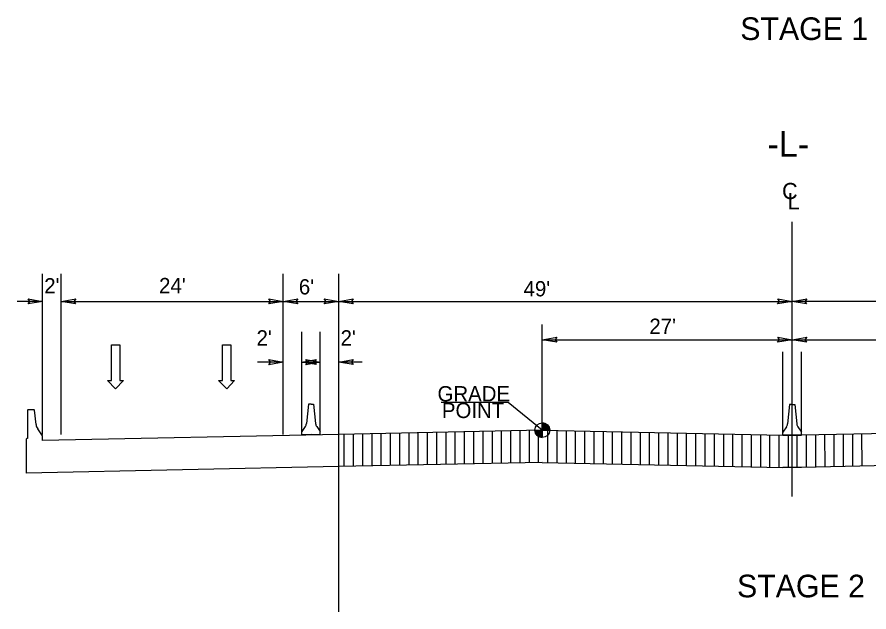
# Model space of a CAD drawing. Extents: x 2241081 to 2251104, y 658534 to 663427.
# Drawn here: x 2245916 to 2246330.3, y 660065.4 to 660354.9 of the extents above; entities that cross this region are included whole.
import ezdxf

# ---------------------------------------------------------------- set-up
doc = ezdxf.new("R2010")
doc.units = 0
for name, color, linetype in [('Prop Dimension', 7, 'Continuous'), ('Prop Dimension Text', 7, 'Continuous'), ('Prop Lane Arrow CELL', 7, 'Continuous'), ('Prop Roadway Bridge', 7, 'Continuous'), ('Typical Grade Point Symbol CELL', 7, 'Continuous'), ('Typical Median Barrier CELL', 7, 'Continuous'), ('Typical Terminator CELL', 7, 'Continuous'), ('Typical Text Centerline CELL', 7, 'Continuous'), ('Typical Text Grade Point CELL', 7, 'Continuous'), ('Typical Text Label CELL', 7, 'Continuous')]:
    doc.layers.add(name, color=color, linetype=linetype)

msp = doc.modelspace()

# ---------------------------------------------------------------- linework, layer by layer
at = {"layer": 'Prop Dimension'}
for p, q in [((2245928.42, 660151.8), (2245928.42, 660229.9)), ((2245937.42, 660151.8), (2245937.42, 660229.9)), ((2246045.42, 660164.32), (2246045.42, 660229.9)), ((2246072.42, 660151.8), (2246072.42, 660229.9)), ((2246054.42, 660164.32), (2246054.42, 660201.64)), ((2246063.42, 660164.32), (2246063.42, 660201.64)), ((2246288.42, 660152.98), (2246288.42, 660191.92)), ((2246297.42, 660152.98), (2246297.42, 660191.92))]:
    msp.add_line(p, q, dxfattribs=at)
at = {"layer": 'Prop Dimension Text'}
for p, q in [((2246045.42, 660151.8), (2246045.42, 660228.78)), ((2246072.42, 660152.36), (2246072.42, 660228.78)), ((2246072.42, 660065.43), (2246072.42, 660228.22)), ((2245928.42, 660216.54), (2245915.96, 660216.54)), ((2245937.42, 660216.54), (2246045.42, 660216.54)), ((2245937.42, 660216.54), (2245946.42, 660216.54)), ((2246045.42, 660216.54), (2246072.42, 660216.54)), ((2246072.42, 660216.54), (2246292.92, 660216.54)), ((2246531.42, 660216.54), (2246292.92, 660216.54)), ((2246171.42, 660153.86), (2246171.42, 660205.36)), ((2246171.42, 660197.89), (2246292.92, 660197.89)), ((2246292.92, 660197.89), (2246414.42, 660197.89)), ((2246054.42, 660152.36), (2246054.42, 660194.7)), ((2246063.42, 660152.36), (2246063.42, 660194.7)), ((2246045.42, 660186.98), (2246032.96, 660186.98)), ((2246054.42, 660186.98), (2246063.42, 660186.98)), ((2246083.84, 660186.98), (2246072.42, 660186.98)), ((2246075.11, 660136.2), (2246075.11, 660151.86)), ((2246079.61, 660136.29), (2246079.61, 660151.95)), ((2246084.11, 660136.38), (2246084.11, 660152.05)), ((2246088.61, 660136.48), (2246088.61, 660152.14)), ((2246093.11, 660136.57), (2246093.11, 660152.23)), ((2246097.61, 660136.66), (2246097.61, 660152.33)), ((2246102.11, 660136.76), (2246102.11, 660152.42)), ((2246106.61, 660136.85), (2246106.61, 660152.51)), ((2246111.11, 660136.94), (2246111.11, 660152.61)), ((2246115.61, 660137.04), (2246115.61, 660152.7)), ((2246120.11, 660137.13), (2246120.11, 660152.79)), ((2246124.61, 660137.22), (2246124.61, 660152.89)), ((2246129.11, 660137.32), (2246129.11, 660152.98)), ((2246133.61, 660137.41), (2246133.61, 660153.08)), ((2246138.11, 660137.51), (2246138.11, 660153.17)), ((2246142.61, 660137.6), (2246142.61, 660153.26)), ((2246147.11, 660137.69), (2246147.11, 660153.36)), ((2246151.61, 660137.79), (2246151.61, 660153.45)), ((2246156.11, 660137.88), (2246156.11, 660153.54)), ((2246160.61, 660137.97), (2246160.61, 660153.64)), ((2246165.11, 660138.07), (2246165.11, 660153.73)), ((2246169.61, 660138.16), (2246169.61, 660153.82)), ((2246174.11, 660138.14), (2246174.11, 660153.81)), ((2246178.61, 660138.05), (2246178.61, 660153.71)), ((2246183.11, 660137.95), (2246183.11, 660153.62)), ((2246187.61, 660137.86), (2246187.61, 660153.53)), ((2246192.11, 660137.77), (2246192.11, 660153.43)), ((2246196.61, 660137.67), (2246196.61, 660153.34)), ((2246201.11, 660137.58), (2246201.11, 660153.24)), ((2246205.61, 660137.49), (2246205.61, 660153.15)), ((2246210.11, 660137.39), (2246210.11, 660153.06)), ((2246214.61, 660137.3), (2246214.61, 660152.96)), ((2246219.11, 660137.21), (2246219.11, 660152.87)), ((2246223.61, 660137.11), (2246223.61, 660152.78)), ((2246228.11, 660137.02), (2246228.11, 660152.68)), ((2246232.61, 660136.93), (2246232.61, 660152.59)), ((2246237.11, 660136.83), (2246237.11, 660152.5)), ((2246241.61, 660136.74), (2246241.61, 660152.4)), ((2246246.11, 660136.64), (2246246.11, 660152.31)), ((2246250.61, 660136.55), (2246250.61, 660152.21)), ((2246255.11, 660136.46), (2246255.11, 660152.12)), ((2246259.61, 660136.36), (2246259.61, 660152.03)), ((2246264.11, 660136.27), (2246264.11, 660151.93)), ((2246268.61, 660136.18), (2246268.61, 660151.84)), ((2246317.89, 660136.19), (2246317.87, 660151.85)), ((2246322.39, 660136.28), (2246322.37, 660151.95)), ((2246326.89, 660136.38), (2246326.87, 660152.04)), ((2246273.11, 660136.08), (2246273.11, 660151.75)), ((2246277.61, 660135.99), (2246277.61, 660151.65)), ((2246282.11, 660135.9), (2246282.11, 660151.56)), ((2246286.61, 660135.8), (2246286.61, 660151.47)), ((2246291.11, 660135.76), (2246291.11, 660151.43)), ((2246295.39, 660135.76), (2246295.37, 660151.43)), ((2246299.89, 660135.82), (2246299.87, 660151.48)), ((2246304.39, 660135.91), (2246304.37, 660151.57)), ((2246308.89, 660136), (2246308.87, 660151.67)), ((2246313.39, 660136.1), (2246313.37, 660151.76))]:
    msp.add_line(p, q, dxfattribs=at)
at = {"layer": 'Prop Lane Arrow CELL'}
for p, q in [((2245961.82, 660177.97), (2245961.82, 660195.33)), ((2245961.82, 660195.33), (2245965.91, 660195.33)), ((2245965.91, 660195.33), (2245965.91, 660177.97)), ((2246015.82, 660177.97), (2246015.82, 660195.33)), ((2246015.82, 660195.33), (2246019.91, 660195.33)), ((2246019.91, 660195.33), (2246019.91, 660177.97)), ((2245963.92, 660174.06), (2245959.95, 660177.97)), ((2245959.95, 660177.97), (2245961.82, 660177.97)), ((2245967.77, 660177.97), (2245963.92, 660174.06)), ((2245965.91, 660177.97), (2245967.77, 660177.97)), ((2246017.92, 660174.06), (2246013.95, 660177.97)), ((2246013.95, 660177.97), (2246015.82, 660177.97)), ((2246021.77, 660177.97), (2246017.92, 660174.06)), ((2246019.91, 660177.97), (2246021.77, 660177.97))]:
    msp.add_line(p, q, dxfattribs=at)
at = {"layer": 'Prop Roadway Bridge'}
for p, q in [((2245921.18, 660163.75), (2245921.01, 660163.59)), ((2245921.01, 660163.59), (2245921.01, 660149.82)), ((2245924.33, 660163.75), (2245921.18, 660163.75)), ((2245924.52, 660163.57), (2245924.33, 660163.75)), ((2245925.25, 660156.6), (2245924.52, 660163.57)), ((2245928.42, 660151.12), (2245926.01, 660154.56)), ((2246171.42, 660153.86), (2246072.42, 660151.8)), ((2246171.42, 660153.86), (2246288.42, 660151.43)), ((2246414.42, 660153.86), (2246297.42, 660151.43)), ((2245920.69, 660149.82), (2245920.36, 660149.49)), ((2245920.36, 660149.49), (2245920.36, 660147.2)), ((2245921.01, 660149.82), (2245920.69, 660149.82)), ((2246072.42, 660151.8), (2245928.42, 660148.81)), ((2245928.42, 660148.81), (2245928.42, 660151.12)), ((2246297.42, 660151.43), (2246288.42, 660151.43)), ((2245920.36, 660147.2), (2245920.36, 660132.98)), ((2246072.42, 660136.14), (2245920.36, 660132.98)), ((2246171.42, 660138.2), (2246072.42, 660136.14)), ((2246171.42, 660138.2), (2246288.42, 660135.76)), ((2246297.42, 660135.76), (2246288.42, 660135.76)), ((2246414.42, 660138.2), (2246297.42, 660135.76))]:
    msp.add_line(p, q, dxfattribs=at)
msp.add_arc((2245929.58, 660157.05), 4.36, 186.011, 214.9912, dxfattribs=at)
at = {"layer": 'Typical Grade Point Symbol CELL'}
for p, q in [((2246171.42, 660153.86), (2246154.73, 660167.32)), ((2246171.43, 660157.44), (2246171.42, 660153.86)), ((2246171.42, 660153.86), (2246171.43, 660157.44)), ((2246167.84, 660153.86), (2246171.42, 660153.86)), ((2246171.42, 660153.86), (2246171.42, 660150.28)), ((2246175, 660153.86), (2246171.42, 660153.86))]:
    msp.add_line(p, q, dxfattribs=at)
for points in [[(2246171.47, 660153.86), (2246171.47, 660157.44), (2246171.47, 660157.44)], [(2246171.55, 660153.86), (2246171.55, 660157.44)], [(2246171.62, 660153.86), (2246171.62, 660157.43)], [(2246171.69, 660153.86), (2246171.69, 660157.43)], [(2246171.76, 660153.86), (2246171.76, 660157.43)], [(2246171.83, 660153.86), (2246171.83, 660157.42)], [(2246171.9, 660153.86), (2246171.9, 660157.41)], [(2246171.98, 660153.86), (2246171.98, 660157.39)], [(2246172.05, 660153.86), (2246172.05, 660157.39)], [(2246172.12, 660153.86), (2246172.12, 660157.37)], [(2246172.19, 660153.86), (2246172.19, 660157.36)], [(2246172.26, 660153.86), (2246172.26, 660157.34)], [(2246172.33, 660153.86), (2246172.33, 660157.32)], [(2246172.4, 660153.86), (2246172.4, 660157.3)], [(2246172.48, 660153.86), (2246172.48, 660157.28)], [(2246172.55, 660153.86), (2246172.55, 660157.26)], [(2246172.62, 660153.86), (2246172.62, 660157.24)], [(2246172.69, 660153.86), (2246172.69, 660157.21)], [(2246172.76, 660153.86), (2246172.76, 660157.18)], [(2246172.83, 660153.86), (2246172.83, 660157.15)], [(2246172.91, 660153.86), (2246172.91, 660157.12)], [(2246172.98, 660153.86), (2246172.98, 660157.08)], [(2246173.05, 660153.86), (2246173.05, 660157.05)], [(2246173.12, 660153.86), (2246173.12, 660157.01)], [(2246173.19, 660153.86), (2246173.19, 660156.97)], [(2246173.26, 660153.86), (2246173.26, 660156.93)], [(2246173.34, 660153.86), (2246173.34, 660156.89)], [(2246173.41, 660153.86), (2246173.41, 660156.84)], [(2246173.48, 660153.86), (2246173.48, 660156.79)], [(2246173.55, 660153.86), (2246173.55, 660156.74)], [(2246173.62, 660153.86), (2246173.62, 660156.69)], [(2246173.69, 660153.86), (2246173.69, 660156.63)], [(2246173.77, 660153.86), (2246173.77, 660156.57)], [(2246173.84, 660153.86), (2246173.84, 660156.5)], [(2246173.91, 660153.86), (2246173.91, 660156.44)], [(2246173.98, 660153.86), (2246173.98, 660156.37)], [(2246174.05, 660153.86), (2246174.05, 660156.29)], [(2246174.12, 660153.86), (2246174.12, 660156.21)], [(2246174.2, 660153.86), (2246174.2, 660156.12)], [(2246174.27, 660153.86), (2246174.27, 660156.03)], [(2246167.88, 660153.35), (2246167.88, 660153.86)], [(2246167.95, 660152.99), (2246167.95, 660153.86)], [(2246168.02, 660152.74), (2246168.02, 660153.86)], [(2246168.09, 660152.54), (2246168.09, 660153.86)], [(2246168.16, 660152.37), (2246168.16, 660153.86)], [(2246168.24, 660152.22), (2246168.24, 660153.86)], [(2246168.31, 660152.1), (2246168.31, 660153.86)], [(2246168.38, 660151.98), (2246168.38, 660153.86)], [(2246168.45, 660151.86), (2246168.45, 660153.86)], [(2246168.52, 660151.76), (2246168.52, 660153.86)], [(2246168.59, 660151.67), (2246168.59, 660153.86)], [(2246168.66, 660151.58), (2246168.66, 660153.86)], [(2246168.74, 660151.49), (2246168.74, 660153.86)], [(2246168.81, 660151.41), (2246168.81, 660153.86)], [(2246168.88, 660151.34), (2246168.88, 660153.86)], [(2246168.95, 660151.27), (2246168.95, 660153.86)], [(2246169.02, 660151.2), (2246169.02, 660153.86)], [(2246169.09, 660151.14), (2246169.09, 660153.86)], [(2246169.17, 660151.08), (2246169.17, 660153.86)], [(2246169.24, 660151.02), (2246169.24, 660153.86)], [(2246169.31, 660150.97), (2246169.31, 660153.86)], [(2246169.38, 660150.92), (2246169.38, 660153.86)], [(2246169.45, 660150.87), (2246169.45, 660153.86)], [(2246169.52, 660150.82), (2246169.52, 660153.86)], [(2246169.6, 660150.78), (2246169.6, 660153.86)], [(2246169.67, 660150.74), (2246169.67, 660153.86)], [(2246169.74, 660150.7), (2246169.74, 660153.86)], [(2246169.81, 660150.66), (2246169.81, 660153.86)], [(2246169.88, 660150.63), (2246169.88, 660153.86)], [(2246169.95, 660150.6), (2246169.95, 660153.86)], [(2246170.03, 660150.57), (2246170.03, 660153.86)], [(2246170.1, 660150.54), (2246170.1, 660153.86)], [(2246170.17, 660150.5), (2246170.17, 660153.86)], [(2246170.24, 660150.48), (2246170.24, 660153.86)], [(2246170.31, 660150.46), (2246170.31, 660153.86)], [(2246170.38, 660150.43), (2246170.38, 660153.86)], [(2246170.46, 660150.42), (2246170.46, 660153.86)], [(2246170.53, 660150.39), (2246170.53, 660153.86)], [(2246170.6, 660150.38), (2246170.6, 660153.86)], [(2246170.67, 660150.36), (2246170.67, 660153.86)], [(2246170.74, 660150.34), (2246170.74, 660153.86)], [(2246170.81, 660150.33), (2246170.81, 660153.86)], [(2246170.88, 660150.32), (2246170.88, 660153.86)], [(2246170.96, 660150.31), (2246170.96, 660153.86)], [(2246171.03, 660150.31), (2246171.03, 660153.86)], [(2246171.1, 660150.3), (2246171.1, 660153.86)], [(2246171.17, 660150.29), (2246171.17, 660153.86)], [(2246171.24, 660150.29), (2246171.24, 660153.86)], [(2246171.31, 660150.28), (2246171.31, 660153.86)], [(2246171.39, 660150.28), (2246171.39, 660150.28), (2246171.39, 660153.86)], [(2246174.34, 660153.86), (2246174.34, 660155.94)], [(2246174.41, 660153.86), (2246174.41, 660155.84)], [(2246174.48, 660153.86), (2246174.48, 660155.72)], [(2246174.55, 660153.86), (2246174.55, 660155.6)], [(2246174.62, 660153.86), (2246174.62, 660155.46)], [(2246174.7, 660153.86), (2246174.7, 660155.31)], [(2246174.77, 660153.86), (2246174.77, 660155.14)], [(2246174.84, 660153.86), (2246174.84, 660154.93)], [(2246174.91, 660153.86), (2246174.91, 660154.67)], [(2246174.98, 660153.86), (2246174.98, 660154.25)]]:
    msp.add_lwpolyline(points, dxfattribs=at)
msp.add_circle((2246171.42, 660153.86), 3.58, dxfattribs=at)
for start, end in [(359.9905, 89.9905), (179.9905, 269.9905)]:
    msp.add_arc((2246171.42, 660153.86), 3.58, start, end, dxfattribs=at)
at = {"layer": 'Typical Median Barrier CELL'}
for p, q in [((2246057.68, 660166.53), (2246056.67, 660157.08)), ((2246058.92, 660166.53), (2246057.68, 660166.53)), ((2246058.92, 660166.53), (2246060.16, 660166.53)), ((2246060.16, 660166.53), (2246061.16, 660157.08)), ((2246291.68, 660166.32), (2246290.68, 660156.88)), ((2246292.92, 660166.32), (2246291.68, 660166.32)), ((2246292.92, 660166.32), (2246294.16, 660166.32)), ((2246294.16, 660166.32), (2246295.16, 660156.88)), ((2246056.13, 660155.63), (2246054.42, 660153.18)), ((2246054.42, 660151.63), (2246054.42, 660153.18)), ((2246058.92, 660152.25), (2246058.92, 660152.25)), ((2246061.7, 660155.63), (2246063.42, 660153.18)), ((2246063.42, 660151.63), (2246063.42, 660153.18)), ((2246290.13, 660155.43), (2246288.42, 660152.98)), ((2246288.42, 660151.43), (2246288.42, 660152.98)), ((2246292.92, 660152.05), (2246292.92, 660152.05)), ((2246295.7, 660155.43), (2246297.42, 660152.98)), ((2246297.42, 660151.43), (2246297.42, 660152.98)), ((2246063.42, 660151.63), (2246054.42, 660151.63)), ((2246288.42, 660151.43), (2246297.42, 660151.43))]:
    msp.add_line(p, q, dxfattribs=at)
for centre, start, end in [((2246053.59, 660157.41), 325.0062, 353.9447), ((2246064.25, 660157.41), 186.0552, 214.996), ((2246287.59, 660157.21), 325.0038, 353.9447), ((2246298.25, 660157.21), 186.0552, 214.9936)]:
    msp.add_arc(centre, 3.1, start, end, dxfattribs=at)
at = {"layer": 'Typical Terminator CELL'}
for points in [[(2245921.39, 660217.75), (2245928.42, 660216.54), (2245921.35, 660215.29), (2245922.25, 660216.54)], [(2245944.45, 660215.33), (2245937.42, 660216.54), (2245944.49, 660217.79), (2245943.59, 660216.54)], [(2246038.39, 660217.75), (2246045.42, 660216.54), (2246038.35, 660215.29), (2246039.25, 660216.54)], [(2246052.45, 660215.33), (2246045.42, 660216.54), (2246052.49, 660217.79), (2246051.59, 660216.54)], [(2246065.39, 660217.75), (2246072.42, 660216.54), (2246065.35, 660215.29), (2246066.25, 660216.54)], [(2246079.45, 660215.33), (2246072.42, 660216.54), (2246079.49, 660217.79), (2246078.59, 660216.54)], [(2246285.89, 660217.75), (2246292.92, 660216.54), (2246285.85, 660215.29), (2246286.75, 660216.54)], [(2246299.95, 660215.33), (2246292.92, 660216.54), (2246299.99, 660217.79), (2246299.09, 660216.54)], [(2246178.45, 660196.68), (2246171.42, 660197.89), (2246178.49, 660199.14), (2246177.59, 660197.89)], [(2246285.89, 660199.1), (2246292.92, 660197.89), (2246285.85, 660196.64), (2246286.75, 660197.89)], [(2246299.95, 660196.68), (2246292.92, 660197.89), (2246299.99, 660199.14), (2246299.09, 660197.89)], [(2246038.39, 660188.2), (2246045.42, 660186.98), (2246038.35, 660185.73), (2246039.25, 660186.98)], [(2246061.45, 660185.77), (2246054.42, 660186.98), (2246061.49, 660188.23), (2246060.59, 660186.98)], [(2246056.39, 660188.2), (2246063.42, 660186.98), (2246056.35, 660185.73), (2246057.25, 660186.98)], [(2246079.45, 660185.77), (2246072.42, 660186.98), (2246079.49, 660188.23), (2246078.59, 660186.98)]]:
    msp.add_lwpolyline(points, close=True, dxfattribs=at)
at = {"layer": 'Typical Text Centerline CELL'}
msp.add_line((2246292.92, 660121.53), (2246292.92, 660255.23), dxfattribs=at)
at = {"layer": 'Typical Text Grade Point CELL'}
msp.add_line((2246154.73, 660167.32), (2246122.22, 660167.32), dxfattribs=at)

# ---------------------------------------------------------------- texts
at = {"layer": 'Prop Dimension Text'}
for s, height, rotation, p in [('-L-', 12.5, 0.0349, (2246280.84, 660286.86)), ("2'", 7.425, 359.9999, (2245929.19, 660220.4)), ("24'", 7.425, 359.9999, (2245985.04, 660220.51)), ("6'", 7.425, 359.9999, (2246053.01, 660219.91)), ("49'", 7.425, 359.9999, (2246162.3, 660218.97)), ("27'", 7.425, 359.9999, (2246223.47, 660200.72)), ("2'", 7.425, 359.9999, (2246032.42, 660195.05)), ("2'", 7.425, 359.9999, (2246073.32, 660195.05))]:
    msp.add_text(s, height=height, rotation=rotation, dxfattribs=at).set_placement(p)
at = {"layer": 'Typical Text Centerline CELL'}
for s, rotation, p in [('C', 359.9999, (2246288, 660266.28)), ('L', 359.9468, (2246290.73, 660261.33))]:
    msp.add_text(s, height=7.88, rotation=rotation, dxfattribs=at).set_placement(p)
at = {"layer": 'Typical Text Grade Point CELL'}
for s, p in [('GRADE', (2246120.43, 660167.87)), ('POINT', (2246122.57, 660159.77))]:
    msp.add_text(s, height=7.425, rotation=359.9999, dxfattribs=at).set_placement(p)
at = {"layer": 'Typical Text Label CELL'}
for s, p in [('STAGE 1', (2246267.69, 660343.69)), ('STAGE 2', (2246266.11, 660072.54))]:
    msp.add_text(s, height=11.011, dxfattribs=at).set_placement(p)

doc.saveas('drawing.dxf')
